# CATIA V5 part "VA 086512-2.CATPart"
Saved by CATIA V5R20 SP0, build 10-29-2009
Part number: VA 086512-2
Revision: ANY
Definition: UNKNOWN
Nomenclature: VA 086512-2
Source: Unknown
Bounding box of the stored display mesh (mm): x -3.804 to 3.804, y 0.1 to 12.1, z -4 to 4
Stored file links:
  C:\Users\Utente\Desktop\IO LAVORO\3D X SITO CF\CUMSA\3D files VA\VA 086512\VA 086512-2.CATPart
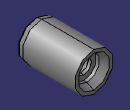
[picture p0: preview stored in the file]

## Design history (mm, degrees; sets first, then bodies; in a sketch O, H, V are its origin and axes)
Body1 "Revolución1" (main body)
  Solid1: solid without history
